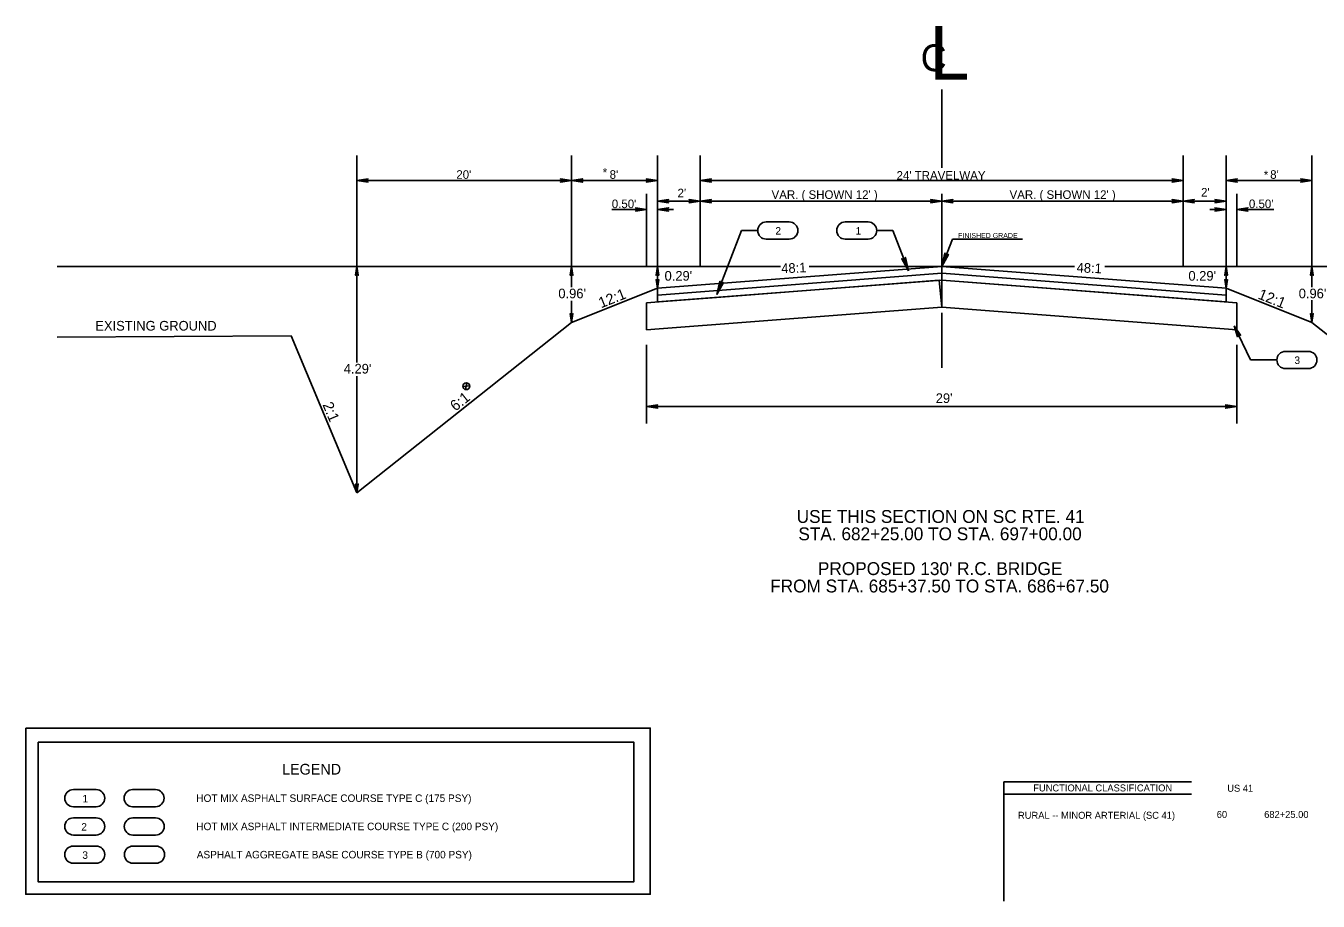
# Model space of a CAD drawing. Extents: x -8855 to -7045, y 42908 to 43943.
# Drawn here: x -8855 to -7651, y 42908 to 43724 of the extents above; entities that cross this region are included whole.
import ezdxf

# ---------------------------------------------------------------- set-up
doc = ezdxf.new("R2010")
doc.units = 0
for name, color, linetype in [('Default', 7, 'Continuous'), ('RD_EX_Misc', 7, 'Continuous'), ('RD_SHT_Bndy', 7, 'Continuous'), ('RD_SHT_TX', 7, 'Continuous'), ('RD_Sketch5', 7, 'Continuous'), ('RD_TX_TypSect', 7, 'Continuous')]:
    doc.layers.add(name, color=color, linetype=linetype)

msp = doc.modelspace()

# ---------------------------------------------------------------- linework, layer by layer
at = {"layer": 'Default'}
for p, q in [((-8825.7, 43499.3), (-8151.6, 43499.3)), ((-8125.1, 43499.3), (-7877.7, 43499.3)), ((-7849.3, 43499.3), (-7239.8, 43499.3)), ((-8266.4, 43479), (-8346.4, 43447.2)), ((-7736.4, 43479), (-7656.4, 43447.2)), ((-8346.4, 43447.2), (-8546.4, 43288.5)), ((-7656.4, 43447.2), (-7589.4, 43394.1)), ((-8825.7, 43433.4), (-8607.8, 43434.7)), ((-8607.8, 43434.7), (-8546.4, 43288.5))]:
    msp.add_line(p, q, dxfattribs=at)
for points in [[(-8546.4, 43579.4), (-8536, 43580.9), (-8537.6, 43579.4), (-8536, 43577.9)], [(-8346.4, 43579.4), (-8356.8, 43577.9), (-8355.2, 43579.4), (-8356.8, 43580.9)], [(-8346.4, 43579.4), (-8336, 43580.9), (-8337.6, 43579.4), (-8336, 43577.9)], [(-8266.4, 43579.4), (-8276.8, 43577.9), (-8275.2, 43579.4), (-8276.8, 43580.9)], [(-8226.4, 43579.4), (-8216, 43580.9), (-8217.6, 43579.4), (-8216, 43577.9)], [(-7776.4, 43579.4), (-7786.8, 43580.9), (-7785.2, 43579.4), (-7786.8, 43577.9)], [(-7736.4, 43579.4), (-7726, 43577.9), (-7727.6, 43579.4), (-7726, 43580.9)], [(-7656.4, 43579.4), (-7666.8, 43580.9), (-7665.2, 43579.4), (-7666.8, 43577.9)], [(-8276.4, 43552.5), (-8286.8, 43551), (-8285.2, 43552.5), (-8286.8, 43554)], [(-8266.4, 43560.2), (-8256, 43561.7), (-8257.6, 43560.2), (-8256, 43558.7)], [(-8266.4, 43552.5), (-8256, 43554), (-8257.6, 43552.5), (-8256, 43551)], [(-8226.4, 43560.2), (-8236.8, 43558.7), (-8235.2, 43560.2), (-8236.8, 43561.7)], [(-8226.4, 43560.2), (-8216, 43561.7), (-8217.6, 43560.2), (-8216, 43558.7)], [(-8001.4, 43560.2), (-8011.8, 43561.7), (-8010.2, 43560.2), (-8011.8, 43558.7)], [(-8001.4, 43560.2), (-7991, 43561.7), (-7992.6, 43560.2), (-7991, 43558.7)], [(-7776.4, 43560.2), (-7786.8, 43561.7), (-7785.2, 43560.2), (-7786.8, 43558.7)], [(-7776.4, 43560.2), (-7766, 43558.7), (-7767.6, 43560.2), (-7766, 43561.7)], [(-7736.4, 43560.2), (-7746.8, 43561.7), (-7745.2, 43560.2), (-7746.8, 43558.7)], [(-7736.4, 43552.5), (-7746.8, 43554), (-7745.2, 43552.5), (-7746.8, 43551)], [(-7726.4, 43552.5), (-7716, 43551), (-7717.6, 43552.5), (-7716, 43554)], [(-8001.4, 43493), (-8001.4, 43486.7), (-8266.4, 43466.3), (-8266.4, 43472.7)], [(-8001.4, 43493), (-8001.4, 43486.7), (-7736.4, 43466.3), (-7736.4, 43472.7)], [(-7728.8, 43443.9), (-7725.7, 43433.9), (-7725, 43436), (-7722.9, 43435.2)], [(-8276.4, 43368.8), (-8266, 43370.3), (-8267.6, 43368.8), (-8266, 43367.3)], [(-7726.4, 43368.8), (-7736.8, 43367.3), (-7735.2, 43368.8), (-7736.8, 43370.3)]]:
    msp.add_lwpolyline(points, close=True, dxfattribs=at)
at = {"layer": 'RD_EX_Misc'}
for p, q in [((-8001.4, 43664.2), (-8001.4, 43591.4)), ((-8546.4, 43499.3), (-8546.4, 43602.7)), ((-8346.4, 43499.3), (-8346.4, 43602.7)), ((-8266.4, 43499.3), (-8266.4, 43602.7)), ((-8226.4, 43499.3), (-8226.4, 43602.7)), ((-7776.4, 43499.3), (-7776.4, 43602.7)), ((-7736.4, 43499.3), (-7736.4, 43602.7)), ((-7656.4, 43499.3), (-7656.4, 43602.7)), ((-8346.4, 43579.4), (-8546.4, 43579.4)), ((-8346.4, 43579.4), (-8266.4, 43579.4)), ((-8226.4, 43579.4), (-7776.4, 43579.4)), ((-7656.4, 43579.4), (-7736.4, 43579.4)), ((-8276.4, 43499.3), (-8276.4, 43567)), ((-8001.4, 43567), (-8001.4, 43499.3)), ((-7726.4, 43499.3), (-7726.4, 43567)), ((-8309, 43552.5), (-8276.4, 43552.5)), ((-8266.4, 43560.2), (-8226.4, 43560.2)), ((-8266.4, 43552.5), (-8251.4, 43552.5)), ((-8001.4, 43560.2), (-8226.4, 43560.2)), ((-8001.4, 43560.2), (-7776.4, 43560.2)), ((-7736.4, 43560.2), (-7776.4, 43560.2)), ((-7736.4, 43552.5), (-7751.4, 43552.5)), ((-7691.8, 43552.5), (-7726.4, 43552.5)), ((-8164.9, 43540.8), (-8143.5, 43540.8)), ((-8091.3, 43540.8), (-8070, 43540.8)), ((-8172.9, 43532.8), (-8187.9, 43532.8)), ((-8062, 43532.8), (-8047, 43532.8)), ((-8143.5, 43524.8), (-8164.9, 43524.8)), ((-8070, 43524.8), (-8091.3, 43524.8)), ((-8546.4, 43499.3), (-8546.4, 43410)), ((-8346.4, 43499.3), (-8346.4, 43480.1)), ((-8266.4, 43479), (-8001.4, 43499.3)), ((-8266.4, 43499.3), (-8266.4, 43479)), ((-8001.4, 43493), (-8266.4, 43472.7)), ((-8001.4, 43499.3), (-8001.4, 43493)), ((-7736.4, 43479), (-8001.4, 43499.3)), ((-8001.4, 43499.3), (-8001.4, 43493)), ((-8001.4, 43493), (-7736.4, 43472.7)), ((-7736.4, 43499.3), (-7736.4, 43479)), ((-7656.4, 43499.3), (-7656.4, 43480.1)), ((-8346.4, 43485.3), (-8346.4, 43480.1)), ((-8266.4, 43472.7), (-8266.4, 43479)), ((-8003.7, 43486.6), (-8211.4, 43470.5)), ((-8001.4, 43461.5), (-8003.7, 43486.6)), ((-8001.4, 43486.7), (-8001.4, 43461.5)), ((-8001.4, 43486.7), (-8001.4, 43461.5)), ((-7736.4, 43472.7), (-7736.4, 43479)), ((-7656.4, 43485.3), (-7656.4, 43480.1)), ((-8346.4, 43467.2), (-8346.4, 43452.4)), ((-8346.4, 43467.2), (-8346.4, 43447.2)), ((-7656.4, 43467.8), (-7656.4, 43447.2)), ((-8276.4, 43465.6), (-8276.4, 43440.3)), ((-8001.4, 43456.2), (-8001.4, 43404.8)), ((-7726.4, 43440.3), (-7726.4, 43465.5)), ((-7656.4, 43462.1), (-7656.4, 43447.2)), ((-7713.7, 43412.2), (-7728.8, 43443.9)), ((-8276.4, 43426.3), (-8276.4, 43353)), ((-7726.4, 43426.3), (-7726.4, 43353)), ((-7681.1, 43420.2), (-7659.8, 43420.2)), ((-8546.4, 43415.2), (-8546.4, 43410)), ((-7689.1, 43412.2), (-7713.7, 43412.2)), ((-8546.4, 43397.1), (-8546.4, 43382.3)), ((-8546.4, 43397.1), (-8546.4, 43288.5)), ((-7659.8, 43404.2), (-7681.1, 43404.2)), ((-8810.7, 43011.9), (-8789.4, 43011.9)), ((-8734.1, 43011.9), (-8755.5, 43011.9)), ((-8789.4, 42995.9), (-8810.7, 42995.9)), ((-8810.7, 42985.6), (-8789.4, 42985.6)), ((-8755.5, 42995.9), (-8734.1, 42995.9)), ((-8789.4, 42969.6), (-8810.7, 42969.6)), ((-8810.7, 42959.3), (-8789.4, 42959.3)), ((-8755.1, 42959.3), (-8733.7, 42959.3)), ((-8755.1, 42959.3), (-8733.7, 42959.3)), ((-8789.4, 42943.3), (-8810.7, 42943.3)), ((-8733.7, 42943.3), (-8755.1, 42943.3)), ((-8733.7, 42943.3), (-8755.1, 42943.3))]:
    msp.add_line(p, q, dxfattribs=at)
for points in [[(-8187.9, 43532.8), (-8211, 43473.2)], [(-8047, 43532.8), (-8032.4, 43495.3)], [(-7991.5, 43524.8), (-8001.4, 43499.3)], [(-7926.1, 43524.8), (-7991.5, 43524.8)], [(-7726.4, 43465.5), (-7738.3, 43466.5), (-8001.4, 43486.7)], [(-8211.4, 43470.5), (-8264.7, 43466.5), (-8276.4, 43465.6)], [(-8276.4, 43440.3), (-8264.7, 43441.2), (-8001.4, 43461.5)], [(-8001.4, 43461.5), (-7738.3, 43441.2), (-7726.4, 43440.3)], [(-8276.4, 43368.8), (-7726.4, 43368.8)], [(-8734, 42985.5), (-8755.3, 42985.5)], [(-8755.3, 42969.5), (-8734, 42969.5)]]:
    msp.add_lwpolyline(points, dxfattribs=at)
for points in [[(-8546.4, 43499.3), (-8547.6, 43491.2), (-8546.4, 43492.5), (-8545.2, 43491.2)], [(-8346.4, 43499.3), (-8347.6, 43491.2), (-8346.4, 43492.5), (-8345.2, 43491.2)], [(-8266.4, 43499.3), (-8265.2, 43491.2), (-8266.4, 43492.5), (-8267.6, 43491.2)], [(-7736.4, 43499.3), (-7737.6, 43491.2), (-7736.4, 43492.5), (-7735.2, 43491.2)], [(-7656.4, 43499.3), (-7657.6, 43491.2), (-7656.4, 43492.5), (-7655.2, 43491.2)], [(-8266.4, 43479), (-8265.2, 43487.1), (-8266.4, 43485.9), (-8267.6, 43487.1)], [(-7736.4, 43479), (-7737.6, 43487.1), (-7736.4, 43485.9), (-7735.2, 43487.1)], [(-8346.4, 43447.2), (-8345.2, 43455.4), (-8346.4, 43454.1), (-8347.6, 43455.4)], [(-7656.4, 43447.2), (-7655.2, 43455.4), (-7656.4, 43454.1), (-7657.6, 43455.4)], [(-8546.4, 43288.5), (-8545.2, 43296.6), (-8546.4, 43295.4), (-8547.6, 43296.6)], [(-8855, 43069.2), (-8273, 43069.2), (-8273, 42914.4), (-8855, 42914.4)], [(-8843.5, 43056), (-8288.3, 43056), (-8288.3, 42926), (-8843.5, 42926)]]:
    msp.add_lwpolyline(points, close=True, dxfattribs=at)
for centre, start, end in [((-8164.9, 43532.8), 90, 270), ((-8143.5, 43532.8), 270, 90), ((-8091.3, 43532.8), 90, 270), ((-8070, 43532.8), 270, 90), ((-7681.1, 43412.2), 90, 270), ((-7659.8, 43412.2), 270, 90), ((-8810.7, 43003.9), 90, 270), ((-8789.4, 43003.9), 270, 90), ((-8755.5, 43003.9), 90, 270), ((-8734.1, 43003.9), 270, 90), ((-8810.7, 42977.6), 90, 270), ((-8789.4, 42977.6), 270, 90), ((-8755.3, 42977.5), 90, 270), ((-8734, 42977.5), 270, 90), ((-8810.7, 42951.3), 90, 270), ((-8789.4, 42951.3), 270, 90), ((-8755.1, 42951.3), 90, 270), ((-8755.1, 42951.3), 90, 270), ((-8733.7, 42951.3), 270, 90), ((-8733.7, 42951.3), 270, 90)]:
    msp.add_arc(centre, 8, start, end, dxfattribs=at)
at = {"layer": 'RD_SHT_Bndy'}
for p, q in [((-7943.5, 43019.1), (-7768.5, 43019.1)), ((-7943.5, 42908), (-7943.5, 43019.1)), ((-7943.5, 43007.8), (-7768.5, 43007.8))]:
    msp.add_line(p, q, dxfattribs=at)
at = {"layer": 'RD_Sketch5'}
for points in [[(-8032.4, 43495.3), (-8035.3, 43507.8), (-8036.3, 43505.3), (-8038.7, 43506.5)], [(-8001.4, 43499.3), (-7998.5, 43511.8), (-7997.5, 43509.3), (-7995.1, 43510.5)], [(-8211, 43473.2), (-8208.2, 43485.6), (-8207.2, 43483.2), (-8204.8, 43484.3)]]:
    msp.add_lwpolyline(points, close=True, dxfattribs=at)
at = {"layer": 'RD_TX_TypSect'}
for p, q in [((-8447.7, 43387.4), (-8441.3, 43388.2)), ((-8445.1, 43384.7), (-8444, 43390.9))]:
    msp.add_line(p, q, dxfattribs=at)
msp.add_circle((-8444.5, 43387.8), 3.2, dxfattribs=at)

# ---------------------------------------------------------------- texts
at = {"layer": 'RD_EX_Misc'}
for s, height, p in [('L', 50, (-8012.7, 43673.5)), ('C', 25, (-8021, 43681.3)), ("20'", 8, (-8453.8, 43581)), ('*', 8, (-8317.4, 43583)), ("8'", 8, (-8310.9, 43581)), ('*', 8, (-7701.2, 43580.7)), ("8'", 8, (-7695.3, 43581)), ("2'", 8, (-8247.6, 43563.8)), ("VAR. ( SHOWN 12' )", 8, (-8160, 43562.3)), ("VAR. ( SHOWN 12' )", 8, (-7938.2, 43562.3)), ("2'", 8, (-7759.7, 43564.5)), ("0.50'", 8, (-8308.9, 43553.7)), ("0.50'", 8, (-7715.1, 43553.7)), ('2', 7, (-8156.4, 43529)), ('1', 7, (-8081.7, 43529)), ("0.29'", 9, (-8259.7, 43486.1)), ("0.29'", 9, (-7771.5, 43486.1)), ("0.96'", 9, (-8358.7, 43469.7)), ("0.96'", 9, (-7668.7, 43469.7)), ('EXISTING GROUND ', 9, (-8790.2, 43439.6)), ("4.29'", 9, (-8558.7, 43399.6)), ('3', 7, (-7672.7, 43408.5)), ("29'", 9, (-8007, 43372.1)), ('USE THIS SECTION ON SC RTE. 41 ', 12, (-8136.6, 43260.4)), ('STA. 682+25.00 TO STA. 697+00.00', 12, (-8135, 43244.2)), ("PROPOSED 130' R.C. BRIDGE", 12, (-8116.8, 43211.8)), ('FROM STA. 685+37.50 TO STA. 686+67.50', 12, (-8161.3, 43195.6)), ('LEGEND', 10, (-8616.2, 43025.9)), ('1', 7, (-8802.2, 43000)), ('HOT MIX ASPHALT SURFACE COURSE TYPE C (175 PSY)', 7, (-8696.1, 43000.4)), ('2', 7, (-8803.3, 42973.7)), ('HOT MIX ASPHALT INTERMEDIATE COURSE TYPE C (200 PSY)', 7, (-8696.1, 42974.1)), ('3', 7, (-8802.3, 42947.4)), ('ASPHALT AGGREGATE BASE COURSE TYPE B (700 PSY)', 7, (-8695.7, 42947.8))]:
    msp.add_text(s, height=height, dxfattribs=at).set_placement(p)
for s, height, rotation, p in [("24' TRAVELWAY", 8, 360, (-8043.5, 43580.2)), ('FINISHED GRADE', 4.722, 0.0434, (-7986.1, 43525.8)), ('48:1', 9, 2.3821, (-8150.8, 43493)), ('48:1', 9, 357.6179, (-7875.8, 43493.9)), ('12:1', 10, 21.6447, (-8318.9, 43460.3)), ('12:1', 10, 338.3553, (-7707.4, 43469.6)), ('2:1', 10, 292.7822, (-8578.7, 43370.6)), ('6:1', 10, 38.4376, (-8454.6, 43364))]:
    msp.add_text(s, height=height, rotation=rotation, dxfattribs=at).set_placement(p)
at = {"layer": 'RD_SHT_TX'}
for s, p in [('FUNCTIONAL CLASSIFICATION', (-7916.1, 43010.2)), ('US 41', (-7735.3, 43009.9)), ('RURAL -- MINOR ARTERIAL (SC 41)', (-7930.3, 42984.7)), ('60', (-7745.1, 42985.5)), ('682+25.00', (-7700.9, 42985.5))]:
    msp.add_text(s, height=6.5, dxfattribs=at).set_placement(p)

doc.saveas('drawing.dxf')
